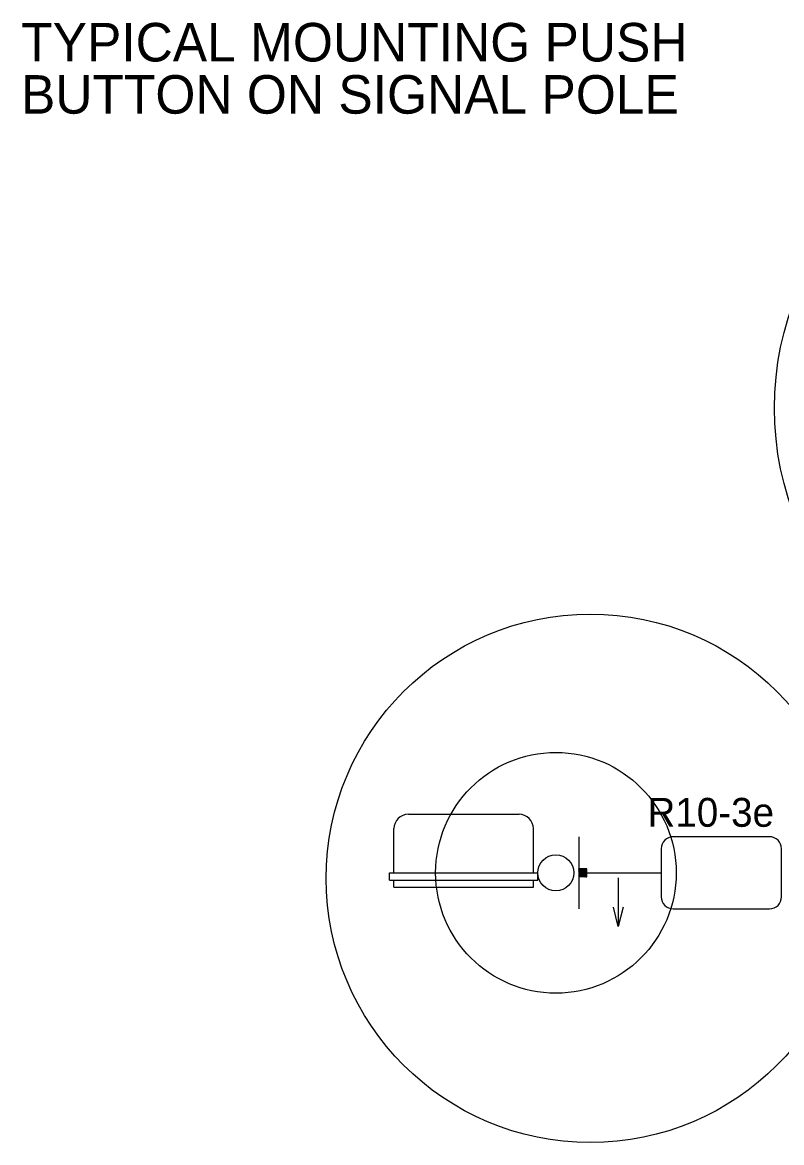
# Model space of a CAD drawing. Extents: x 418532 to 420296, y -565948 to -565286.
# Drawn here: x 419573.9 to 419692.3, y -565790.4 to -565616 of the extents above; entities that cross this region are included whole.
import ezdxf

# ---------------------------------------------------------------- set-up
doc = ezdxf.new("R2010")
doc.units = 0
doc.layers.add('R_Draft', color=7, linetype='Continuous')
doc.layers.add('T_Drafting', color=7, linetype='Continuous')

msp = doc.modelspace()

# ---------------------------------------------------------------- linework, layer by layer
at = {"layer": 'T_Drafting'}
for p, q in [((419634.1, -565739.29), (419651.35, -565739.29)), ((419631.85, -565748.42), (419631.85, -565741.54)), ((419653.6, -565748.42), (419653.6, -565741.54)), ((419660.66, -565742.79), (419660.66, -565754.04)), ((419690.41, -565742.79), (419675.39, -565742.79)), ((419673.51, -565744.67), (419673.51, -565752.17)), ((419692.29, -565752.17), (419692.29, -565744.67)), ((419631.16, -565748.42), (419654.28, -565748.42)), ((419631.16, -565749.54), (419631.16, -565748.42)), ((419654.28, -565749.54), (419654.28, -565748.42)), ((419661.91, -565747.79), (419660.66, -565747.79)), ((419660.66, -565749.04), (419661.9, -565747.79)), ((419660.66, -565749.02), (419661.88, -565747.79)), ((419660.66, -565748.99), (419661.86, -565747.79)), ((419660.66, -565748.97), (419661.84, -565747.79)), ((419660.66, -565748.95), (419661.82, -565747.79)), ((419660.66, -565748.93), (419661.8, -565747.79)), ((419660.66, -565748.91), (419661.78, -565747.79)), ((419660.66, -565748.89), (419661.76, -565747.79)), ((419660.66, -565748.87), (419661.73, -565747.79)), ((419660.66, -565748.85), (419661.71, -565747.79)), ((419660.66, -565748.83), (419661.69, -565747.79)), ((419660.66, -565748.8), (419661.67, -565747.79)), ((419660.66, -565748.78), (419661.65, -565747.79)), ((419660.66, -565748.76), (419661.63, -565747.79)), ((419660.66, -565748.74), (419661.61, -565747.79)), ((419660.66, -565748.72), (419661.59, -565747.79)), ((419660.66, -565748.7), (419661.56, -565747.79)), ((419660.66, -565748.68), (419661.54, -565747.79)), ((419660.66, -565748.66), (419661.52, -565747.79)), ((419660.66, -565748.63), (419661.5, -565747.79)), ((419660.66, -565748.61), (419661.48, -565747.79)), ((419660.66, -565748.59), (419661.46, -565747.79)), ((419660.66, -565748.57), (419661.44, -565747.79)), ((419660.66, -565748.55), (419661.42, -565747.79)), ((419660.66, -565748.53), (419661.39, -565747.79)), ((419660.66, -565748.51), (419661.37, -565747.79)), ((419660.66, -565748.49), (419661.35, -565747.79)), ((419660.66, -565748.46), (419661.33, -565747.79)), ((419660.66, -565748.44), (419661.31, -565747.79)), ((419660.66, -565748.42), (419661.29, -565747.79)), ((419660.66, -565748.4), (419661.27, -565747.79)), ((419660.66, -565748.38), (419661.25, -565747.79)), ((419660.66, -565748.36), (419661.23, -565747.79)), ((419660.66, -565748.34), (419661.2, -565747.79)), ((419660.66, -565748.32), (419661.18, -565747.79)), ((419660.66, -565748.29), (419661.16, -565747.79)), ((419660.66, -565748.27), (419661.14, -565747.79)), ((419660.66, -565748.25), (419661.12, -565747.79)), ((419660.66, -565748.23), (419661.1, -565747.79)), ((419660.66, -565748.21), (419661.08, -565747.79)), ((419660.66, -565748.19), (419661.06, -565747.79)), ((419660.66, -565748.17), (419661.03, -565747.79)), ((419660.66, -565748.15), (419661.01, -565747.79)), ((419660.66, -565748.13), (419660.99, -565747.79)), ((419660.66, -565748.1), (419660.97, -565747.79)), ((419660.66, -565748.08), (419660.95, -565747.79)), ((419660.66, -565748.06), (419660.93, -565747.79)), ((419660.66, -565748.04), (419660.91, -565747.79)), ((419660.66, -565748.02), (419660.89, -565747.79)), ((419660.66, -565748), (419660.86, -565747.79)), ((419660.66, -565747.98), (419660.84, -565747.79)), ((419660.66, -565747.96), (419660.82, -565747.79)), ((419660.66, -565747.93), (419660.8, -565747.79)), ((419660.66, -565747.91), (419660.78, -565747.79)), ((419660.66, -565747.89), (419660.76, -565747.79)), ((419660.66, -565747.87), (419660.74, -565747.79)), ((419660.66, -565747.85), (419660.72, -565747.79)), ((419660.66, -565747.83), (419660.69, -565747.79)), ((419660.66, -565747.81), (419660.67, -565747.79)), ((419661.91, -565749.04), (419660.66, -565749.04)), ((419660.68, -565749.04), (419661.91, -565747.81)), ((419660.7, -565749.04), (419661.91, -565747.83)), ((419660.72, -565749.04), (419661.91, -565747.85)), ((419660.74, -565749.04), (419661.91, -565747.87)), ((419660.76, -565749.04), (419661.91, -565747.89)), ((419660.78, -565749.04), (419661.91, -565747.91)), ((419660.8, -565749.04), (419661.91, -565747.94)), ((419660.82, -565749.04), (419661.91, -565747.96)), ((419660.84, -565749.04), (419661.91, -565747.98)), ((419660.87, -565749.04), (419661.91, -565748)), ((419660.89, -565749.04), (419661.91, -565748.02)), ((419660.91, -565749.04), (419661.91, -565748.04)), ((419660.93, -565749.04), (419661.91, -565748.06)), ((419660.95, -565749.04), (419661.91, -565748.08)), ((419660.97, -565749.04), (419661.91, -565748.11)), ((419660.99, -565749.04), (419661.91, -565748.13)), ((419661.01, -565749.04), (419661.91, -565748.15)), ((419661.04, -565749.04), (419661.91, -565748.17)), ((419661.06, -565749.04), (419661.91, -565748.19)), ((419661.08, -565749.04), (419661.91, -565748.21)), ((419661.1, -565749.04), (419661.91, -565748.23)), ((419661.12, -565749.04), (419661.91, -565748.25)), ((419661.14, -565749.04), (419661.91, -565748.28)), ((419661.16, -565749.04), (419661.91, -565748.3)), ((419661.18, -565749.04), (419661.91, -565748.32)), ((419661.21, -565749.04), (419661.91, -565748.34)), ((419661.23, -565749.04), (419661.91, -565748.36)), ((419661.25, -565749.04), (419661.91, -565748.38)), ((419661.27, -565749.04), (419661.91, -565748.4)), ((419661.29, -565749.04), (419661.91, -565748.42)), ((419661.31, -565749.04), (419661.91, -565748.44)), ((419661.33, -565749.04), (419661.91, -565748.47)), ((419661.35, -565749.04), (419661.91, -565748.49)), ((419661.38, -565749.04), (419661.91, -565748.51)), ((419661.4, -565749.04), (419661.91, -565748.53)), ((419661.42, -565749.04), (419661.91, -565748.55)), ((419661.44, -565749.04), (419661.91, -565748.57)), ((419661.46, -565749.04), (419661.91, -565748.59)), ((419661.48, -565749.04), (419661.91, -565748.61)), ((419661.5, -565749.04), (419661.91, -565748.64)), ((419661.52, -565749.04), (419661.91, -565748.66)), ((419661.54, -565749.04), (419661.91, -565748.68)), ((419661.57, -565749.04), (419661.91, -565748.7)), ((419661.59, -565749.04), (419661.91, -565748.72)), ((419661.61, -565749.04), (419661.91, -565748.74)), ((419661.63, -565749.04), (419661.91, -565748.76)), ((419661.65, -565749.04), (419661.91, -565748.78)), ((419661.67, -565749.04), (419661.91, -565748.81)), ((419661.69, -565749.04), (419661.91, -565748.83)), ((419661.71, -565749.04), (419661.91, -565748.85)), ((419661.74, -565749.04), (419661.91, -565748.87)), ((419661.76, -565749.04), (419661.91, -565748.89)), ((419661.78, -565749.04), (419661.91, -565748.91)), ((419661.8, -565749.04), (419661.91, -565748.93)), ((419661.82, -565749.04), (419661.91, -565748.95)), ((419661.84, -565749.04), (419661.91, -565748.98)), ((419661.86, -565749.04), (419661.91, -565749)), ((419661.88, -565749.04), (419661.91, -565749.02)), ((419661.91, -565749.04), (419661.91, -565747.79)), ((419661.91, -565748.42), (419673.51, -565748.42)), ((419661.91, -565749.04), (419661.91, -565749.04)), ((419666.82, -565749.22), (419666.82, -565756.77)), ((419631.16, -565749.54), (419654.28, -565749.54)), ((419631.85, -565750.67), (419631.85, -565749.54)), ((419631.85, -565750.67), (419653.6, -565750.67)), ((419653.6, -565750.67), (419653.6, -565749.54)), ((419675.39, -565754.04), (419690.41, -565754.04))]:
    msp.add_line(p, q, dxfattribs=at)
msp.add_lwpolyline([(419667.57, -565753.77), (419666.82, -565756.77), (419666.07, -565753.77)], dxfattribs=at)
for centre, radius in [((419738.21, -565676.03), 47.03), ((419662.46, -565749.28), 41.16), ((419657.1, -565748.42), 18.75), ((419657.1, -565748.42), 2.81)]:
    msp.add_circle(centre, radius, dxfattribs=at)
for centre, radius, start, end in [((419634.1, -565741.54), 2.25, 90, 180), ((419651.35, -565741.54), 2.25, 360, 90), ((419675.39, -565744.67), 1.87, 90, 180), ((419690.41, -565744.67), 1.87, 0, 90), ((419675.39, -565752.17), 1.87, 180, 270), ((419690.41, -565752.17), 1.87, 270, 0)]:
    msp.add_arc(centre, radius, start, end, dxfattribs=at)

# ---------------------------------------------------------------- texts
at = {"layer": 'R_Draft'}
for s, p in [('TYPICAL MOUNTING PUSH ', (419573.75, -565622.04)), ('BUTTON ON SIGNAL POLE ', (419573.71, -565630.17))]:
    msp.add_text(s, height=6, dxfattribs=at).set_placement(p)
at = {"layer": 'T_Drafting'}
msp.add_text('R10-3e', height=4.5, dxfattribs=at).set_placement((419671.37, -565741.25))

doc.saveas('drawing.dxf')
